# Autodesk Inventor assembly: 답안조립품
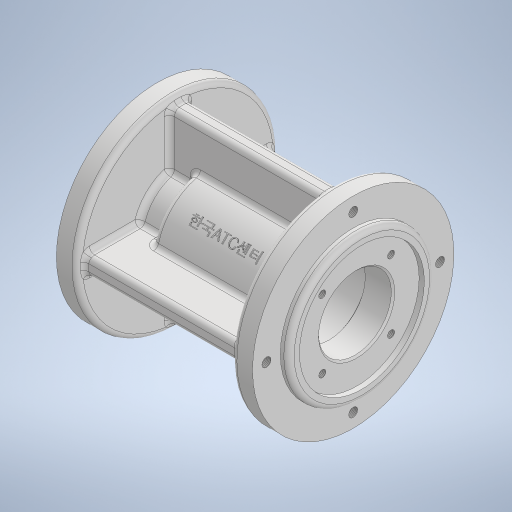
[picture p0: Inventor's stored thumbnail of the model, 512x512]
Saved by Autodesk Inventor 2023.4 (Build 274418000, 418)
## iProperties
Created: 2024-10
Part Number: 답안조립품
Document SubType Name: Assembly
Designer: 11
Author: 11
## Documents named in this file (2)
- C:\Users\11\Desktop\741004V1009\답안조립품.iam
- C:\Users\11\Desktop\741004V1009\본체.ipt
